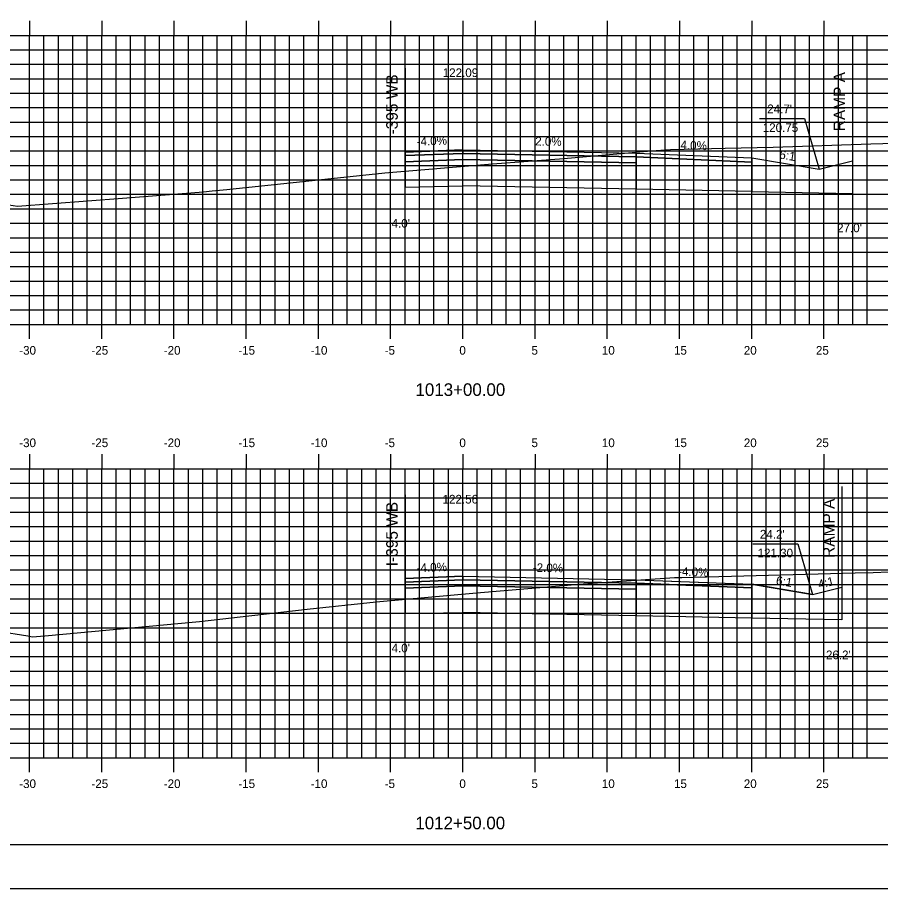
# Model space of a CAD drawing. Extents: x 852625 to 852797, y 365624 to 365734.
# Drawn here: x 852677.7 to 852737.5, y 365624 to 365684.3 of the extents above; entities that cross this region are included whole.
import ezdxf

# ---------------------------------------------------------------- set-up
doc = ezdxf.new("R2010")
doc.units = 0
for name, color, linetype in [('ANNOTATION', 7, 'Continuous'), ('BORDER', 7, 'Continuous'), ('D_Roadway_Centerline', 7, 'Continuous'), ('D_Roadway_Centerline_Text', 7, 'Continuous'), ('D_Roadway_Edge_Shoulder', 7, 'Continuous'), ('D_Roadway_Edge_TW', 7, 'Continuous'), ('D_Roadway_FinishedGrade', 7, 'Continuous'), ('D_Roadway_Pavement', 7, 'Continuous'), ('D_Roadway_SubGrade', 7, 'Continuous'), ('D_Text_Standard', 7, 'Continuous'), ('Default', 7, 'Continuous'), ('H_V ANNOTATION', 7, 'Continuous'), ('MAJOR', 7, 'Continuous'), ('MINOR', 7, 'Continuous'), ('PLOT BOUNDARY', 7, 'Continuous'), ('S_Roadway_Centerline', 7, 'Continuous')]:
    doc.layers.add(name, color=color, linetype=linetype)

msp = doc.modelspace()

# ---------------------------------------------------------------- linework, layer by layer
at = {"layer": 'ANNOTATION'}
for points in [[(852729.095, 365677.281), (852732.205, 365677.281), (852733.216, 365673.776)], [(852728.635, 365647.834), (852731.744, 365647.834), (852732.755, 365644.329)]]:
    msp.add_lwpolyline(points, dxfattribs=at)
at = {"layer": 'BORDER'}
msp.add_lwpolyline([(852633.549, 365627.027), (852793.549, 365627.027), (852793.549, 365732.027), (852633.549, 365732.027)], close=True, dxfattribs=at)
at = {"layer": 'D_Roadway_Centerline'}
for p, q in [((852728.548, 365674.554), (852733.216, 365673.776)), ((852728.548, 365672.214), (852735.524, 365672.088))]:
    msp.add_line(p, q, dxfattribs=at)
for points in [[(852704.548, 365674.954), (852708.548, 365675.114), (852708.55, 365675.114), (852720.549, 365674.874), (852728.548, 365674.554)], [(852733.216, 365673.776), (852735.525, 365674.353)], [(852704.548, 365645.43), (852704.548, 365645.43), (852708.547, 365645.59), (852708.549, 365645.59), (852720.544, 365645.35), (852720.549, 365645.35), (852728.544, 365645.03), (852732.755, 365644.329), (852728.548, 365645.03)], [(852732.755, 365644.329), (852734.789, 365644.837)], [(852734.789, 365642.572), (852728.548, 365642.69)]]:
    msp.add_lwpolyline(points, dxfattribs=at)
at = {"layer": 'D_Roadway_Edge_Shoulder'}
for points in [[(852708.548, 365675.114), (852704.548, 365674.954), (852704.548, 365674.704), (852708.548, 365674.864)], [(852720.548, 365674.874), (852728.548, 365674.554), (852728.548, 365674.26), (852720.549, 365674.624)], [(852708.549, 365645.59), (852704.548, 365645.43), (852704.548, 365645.18), (852708.549, 365645.34)], [(852720.549, 365645.35), (852728.548, 365645.03), (852728.548, 365644.78), (852720.549, 365645.1)]]:
    msp.add_lwpolyline(points, close=True, dxfattribs=at)
at = {"layer": 'D_Roadway_Edge_TW'}
for points in [[(852708.548, 365675.114), (852720.548, 365674.874), (852720.549, 365674.624), (852708.548, 365674.864)], [(852708.549, 365645.59), (852720.549, 365645.35), (852720.549, 365645.1), (852708.549, 365645.34)]]:
    msp.add_lwpolyline(points, close=True, dxfattribs=at)
for points in [[(852720.548, 365674.874), (852720.548, 365674.707)], [(852720.549, 365645.35), (852720.549, 365645.183)]]:
    msp.add_lwpolyline(points, dxfattribs=at)
at = {"layer": 'D_Roadway_FinishedGrade'}
for p, q in [((852708.548, 365675.114), (852708.548, 365674.864)), ((852704.548, 365674.954), (852704.548, 365674.704)), ((852720.549, 365674.874), (852720.549, 365674.624)), ((852728.548, 365674.554), (852728.548, 365674.304)), ((852708.549, 365645.59), (852708.549, 365645.34)), ((852704.548, 365645.43), (852704.548, 365645.18)), ((852720.549, 365645.35), (852720.549, 365645.1)), ((852728.548, 365645.03), (852728.548, 365644.78))]:
    msp.add_line(p, q, dxfattribs=at)
at = {"layer": 'D_Roadway_Pavement'}
for points in [[(852708.548, 365674.864), (852704.548, 365674.704), (852704.548, 365674.287), (852708.548, 365674.447)], [(852708.548, 365674.864), (852720.549, 365674.624), (852720.548, 365674.207), (852708.548, 365674.447)], [(852708.549, 365645.34), (852704.548, 365645.18), (852704.548, 365644.763), (852708.549, 365644.923)], [(852708.549, 365645.34), (852720.549, 365645.1), (852720.549, 365644.683), (852708.549, 365644.923)]]:
    msp.add_lwpolyline(points, close=True, dxfattribs=at)
for points in [[(852720.548, 365674.707), (852720.548, 365674.207)], [(852720.548, 365674.707), (852720.548, 365674.207)], [(852720.549, 365645.183), (852720.549, 365644.683)], [(852720.549, 365645.183), (852720.549, 365644.683)]]:
    msp.add_lwpolyline(points, dxfattribs=at)
at = {"layer": 'D_Roadway_SubGrade'}
for p, q in [((852735.525, 365681.328), (852735.525, 365672.088)), ((852704.548, 365680.765), (852704.548, 365672.534)), ((852734.789, 365651.802), (852734.789, 365642.572)), ((852704.548, 365651.225), (852704.548, 365643.01))]:
    msp.add_line(p, q, dxfattribs=at)
for points in [[(852708.548, 365674.447), (852704.548, 365674.287), (852704.548, 365674.787), (852704.548, 365674.954), (852704.548, 365672.534), (852708.548, 365672.614)], [(852708.548, 365674.447), (852720.548, 365674.207), (852720.548, 365672.374), (852708.548, 365672.614)], [(852720.548, 365674.207), (852720.549, 365674.624), (852728.548, 365674.26), (852728.548, 365674.554), (852728.548, 365672.214), (852720.548, 365672.374)], [(852708.549, 365644.923), (852704.548, 365644.763), (852704.548, 365645.263), (852704.548, 365645.43), (852704.548, 365643.01), (852708.549, 365643.09)], [(852708.549, 365644.923), (852720.549, 365644.683), (852720.549, 365642.85), (852708.549, 365643.09)], [(852720.549, 365644.683), (852720.549, 365645.1), (852728.548, 365644.78), (852728.548, 365645.03), (852728.548, 365642.69), (852720.549, 365642.85)]]:
    msp.add_lwpolyline(points, close=True, dxfattribs=at)
for points in [[(852720.548, 365674.207), (852720.548, 365672.374)], [(852720.549, 365644.683), (852720.549, 365642.85)]]:
    msp.add_lwpolyline(points, dxfattribs=at)
at = {"layer": 'Default'}
for p, q in [((852728.548, 365674.554), (852733.216, 365673.776)), ((852728.548, 365645.03), (852732.755, 365644.329))]:
    msp.add_line(p, q, dxfattribs=at)
at = {"layer": 'MAJOR'}
for p, q in [((852678.548, 365684.029), (852678.548, 365683.027)), ((852683.548, 365684.029), (852683.548, 365683.027)), ((852688.548, 365684.029), (852688.548, 365683.027)), ((852693.548, 365684.029), (852693.548, 365683.027)), ((852698.548, 365684.029), (852698.548, 365683.027)), ((852703.548, 365684.029), (852703.548, 365683.027)), ((852708.548, 365684.029), (852708.548, 365683.027)), ((852713.548, 365684.029), (852713.548, 365683.027)), ((852718.548, 365684.029), (852718.548, 365683.027)), ((852723.548, 365684.029), (852723.548, 365683.027)), ((852728.548, 365684.029), (852728.548, 365683.027)), ((852733.548, 365684.029), (852733.548, 365683.027)), ((852638.548, 365683.027), (852778.548, 365683.027)), ((852638.548, 365683.027), (852778.548, 365683.027)), ((852678.548, 365663.027), (852678.548, 365683.027)), ((852683.548, 365663.027), (852683.548, 365683.027)), ((852688.548, 365663.027), (852688.548, 365683.027)), ((852693.548, 365663.027), (852693.548, 365683.027)), ((852698.548, 365663.027), (852698.548, 365683.027)), ((852703.548, 365663.027), (852703.548, 365683.027)), ((852708.548, 365663.027), (852708.548, 365683.027)), ((852713.548, 365663.027), (852713.548, 365683.027)), ((852718.548, 365663.027), (852718.548, 365683.027)), ((852723.548, 365663.027), (852723.548, 365683.027)), ((852728.548, 365663.027), (852728.548, 365683.027)), ((852733.548, 365663.027), (852733.548, 365683.027)), ((852638.548, 365678.027), (852778.548, 365678.027)), ((852638.548, 365673.027), (852778.548, 365673.027)), ((852638.548, 365668.027), (852778.548, 365668.027)), ((852638.548, 365663.027), (852778.548, 365663.027)), ((852638.548, 365663.027), (852778.548, 365663.027)), ((852678.548, 365662.025), (852678.548, 365663.027)), ((852683.548, 365662.025), (852683.548, 365663.027)), ((852688.548, 365662.025), (852688.548, 365663.027)), ((852693.548, 365662.025), (852693.548, 365663.027)), ((852698.548, 365662.025), (852698.548, 365663.027)), ((852703.548, 365662.025), (852703.548, 365663.027)), ((852708.548, 365662.025), (852708.548, 365663.027)), ((852713.548, 365662.025), (852713.548, 365663.027)), ((852718.548, 365662.025), (852718.548, 365663.027)), ((852723.548, 365662.025), (852723.548, 365663.027)), ((852728.548, 365662.025), (852728.548, 365663.027)), ((852733.548, 365662.025), (852733.548, 365663.027)), ((852678.548, 365654.029), (852678.548, 365653.027)), ((852683.548, 365654.029), (852683.548, 365653.027)), ((852688.548, 365654.029), (852688.548, 365653.027)), ((852693.548, 365654.029), (852693.548, 365653.027)), ((852698.548, 365654.029), (852698.548, 365653.027)), ((852703.548, 365654.029), (852703.548, 365653.027)), ((852708.548, 365654.029), (852708.548, 365653.027)), ((852713.548, 365654.029), (852713.548, 365653.027)), ((852718.548, 365654.029), (852718.548, 365653.027)), ((852723.548, 365654.029), (852723.548, 365653.027)), ((852728.548, 365654.029), (852728.548, 365653.027)), ((852733.548, 365654.029), (852733.548, 365653.027)), ((852638.548, 365653.027), (852778.548, 365653.027)), ((852638.548, 365653.027), (852778.548, 365653.027)), ((852678.548, 365633.027), (852678.548, 365653.027)), ((852683.548, 365633.027), (852683.548, 365653.027)), ((852688.548, 365633.027), (852688.548, 365653.027)), ((852693.548, 365633.027), (852693.548, 365653.027)), ((852698.548, 365633.027), (852698.548, 365653.027)), ((852703.548, 365633.027), (852703.548, 365653.027)), ((852708.548, 365633.027), (852708.548, 365653.027)), ((852713.548, 365633.027), (852713.548, 365653.027)), ((852718.548, 365633.027), (852718.548, 365653.027)), ((852723.548, 365633.027), (852723.548, 365653.027)), ((852728.548, 365633.027), (852728.548, 365653.027)), ((852733.548, 365633.027), (852733.548, 365653.027)), ((852638.548, 365648.027), (852778.548, 365648.027)), ((852638.548, 365643.027), (852778.548, 365643.027)), ((852638.548, 365638.027), (852778.548, 365638.027)), ((852638.548, 365633.027), (852778.548, 365633.027)), ((852638.548, 365633.027), (852778.548, 365633.027)), ((852678.548, 365632.025), (852678.548, 365633.027)), ((852683.548, 365632.025), (852683.548, 365633.027)), ((852688.548, 365632.025), (852688.548, 365633.027)), ((852693.548, 365632.025), (852693.548, 365633.027)), ((852698.548, 365632.025), (852698.548, 365633.027)), ((852703.548, 365632.025), (852703.548, 365633.027)), ((852708.548, 365632.025), (852708.548, 365633.027)), ((852713.548, 365632.025), (852713.548, 365633.027)), ((852718.548, 365632.025), (852718.548, 365633.027)), ((852723.548, 365632.025), (852723.548, 365633.027)), ((852728.548, 365632.025), (852728.548, 365633.027)), ((852733.548, 365632.025), (852733.548, 365633.027))]:
    msp.add_line(p, q, dxfattribs=at)
at = {"layer": 'MINOR'}
for p, q in [((852679.548, 365663.027), (852679.548, 365683.027)), ((852680.548, 365663.027), (852680.548, 365683.027)), ((852681.548, 365663.027), (852681.548, 365683.027)), ((852682.548, 365663.027), (852682.548, 365683.027)), ((852684.548, 365663.027), (852684.548, 365683.027)), ((852685.548, 365663.027), (852685.548, 365683.027)), ((852686.548, 365663.027), (852686.548, 365683.027)), ((852687.548, 365663.027), (852687.548, 365683.027)), ((852689.548, 365663.027), (852689.548, 365683.027)), ((852690.548, 365663.027), (852690.548, 365683.027)), ((852691.548, 365663.027), (852691.548, 365683.027)), ((852692.548, 365663.027), (852692.548, 365683.027)), ((852694.548, 365663.027), (852694.548, 365683.027)), ((852695.548, 365663.027), (852695.548, 365683.027)), ((852696.548, 365663.027), (852696.548, 365683.027)), ((852697.548, 365663.027), (852697.548, 365683.027)), ((852699.548, 365663.027), (852699.548, 365683.027)), ((852700.548, 365663.027), (852700.548, 365683.027)), ((852701.548, 365663.027), (852701.548, 365683.027)), ((852702.548, 365663.027), (852702.548, 365683.027)), ((852704.548, 365663.027), (852704.548, 365683.027)), ((852705.548, 365663.027), (852705.548, 365683.027)), ((852706.548, 365663.027), (852706.548, 365683.027)), ((852707.548, 365663.027), (852707.548, 365683.027)), ((852709.548, 365663.027), (852709.548, 365683.027)), ((852710.548, 365663.027), (852710.548, 365683.027)), ((852711.548, 365663.027), (852711.548, 365683.027)), ((852712.548, 365663.027), (852712.548, 365683.027)), ((852714.548, 365663.027), (852714.548, 365683.027)), ((852715.548, 365663.027), (852715.548, 365683.027)), ((852716.548, 365663.027), (852716.548, 365683.027)), ((852717.548, 365663.027), (852717.548, 365683.027)), ((852719.548, 365663.027), (852719.548, 365683.027)), ((852720.548, 365663.027), (852720.548, 365683.027)), ((852721.548, 365663.027), (852721.548, 365683.027)), ((852722.548, 365663.027), (852722.548, 365683.027)), ((852724.548, 365663.027), (852724.548, 365683.027)), ((852725.548, 365663.027), (852725.548, 365683.027)), ((852726.548, 365663.027), (852726.548, 365683.027)), ((852727.548, 365663.027), (852727.548, 365683.027)), ((852729.548, 365663.027), (852729.548, 365683.027)), ((852730.548, 365663.027), (852730.548, 365683.027)), ((852731.548, 365663.027), (852731.548, 365683.027)), ((852732.548, 365663.027), (852732.548, 365683.027)), ((852734.548, 365663.027), (852734.548, 365683.027)), ((852735.548, 365663.027), (852735.548, 365683.027)), ((852736.548, 365663.027), (852736.548, 365683.027)), ((852638.548, 365682.027), (852778.548, 365682.027)), ((852638.548, 365681.027), (852778.548, 365681.027)), ((852638.548, 365680.027), (852778.548, 365680.027)), ((852638.548, 365679.027), (852778.548, 365679.027)), ((852638.548, 365677.027), (852778.548, 365677.027)), ((852638.548, 365676.027), (852778.548, 365676.027)), ((852638.548, 365675.027), (852778.548, 365675.027)), ((852638.548, 365674.027), (852778.548, 365674.027)), ((852638.548, 365672.027), (852778.548, 365672.027)), ((852638.548, 365671.027), (852778.548, 365671.027)), ((852638.548, 365670.027), (852778.548, 365670.027)), ((852638.548, 365669.027), (852778.548, 365669.027)), ((852638.548, 365667.027), (852778.548, 365667.027)), ((852638.548, 365666.027), (852778.548, 365666.027)), ((852638.548, 365665.027), (852778.548, 365665.027)), ((852638.548, 365664.027), (852778.548, 365664.027)), ((852679.548, 365633.027), (852679.548, 365653.027)), ((852680.548, 365633.027), (852680.548, 365653.027)), ((852681.548, 365633.027), (852681.548, 365653.027)), ((852682.548, 365633.027), (852682.548, 365653.027)), ((852684.548, 365633.027), (852684.548, 365653.027)), ((852685.548, 365633.027), (852685.548, 365653.027)), ((852686.548, 365633.027), (852686.548, 365653.027)), ((852687.548, 365633.027), (852687.548, 365653.027)), ((852689.548, 365633.027), (852689.548, 365653.027)), ((852690.548, 365633.027), (852690.548, 365653.027)), ((852691.548, 365633.027), (852691.548, 365653.027)), ((852692.548, 365633.027), (852692.548, 365653.027)), ((852694.548, 365633.027), (852694.548, 365653.027)), ((852695.548, 365633.027), (852695.548, 365653.027)), ((852696.548, 365633.027), (852696.548, 365653.027)), ((852697.548, 365633.027), (852697.548, 365653.027)), ((852699.548, 365633.027), (852699.548, 365653.027)), ((852700.548, 365633.027), (852700.548, 365653.027)), ((852701.548, 365633.027), (852701.548, 365653.027)), ((852702.548, 365633.027), (852702.548, 365653.027)), ((852704.548, 365633.027), (852704.548, 365653.027)), ((852705.548, 365633.027), (852705.548, 365653.027)), ((852706.548, 365633.027), (852706.548, 365653.027)), ((852707.548, 365633.027), (852707.548, 365653.027)), ((852709.548, 365633.027), (852709.548, 365653.027)), ((852710.548, 365633.027), (852710.548, 365653.027)), ((852711.548, 365633.027), (852711.548, 365653.027)), ((852712.548, 365633.027), (852712.548, 365653.027)), ((852714.548, 365633.027), (852714.548, 365653.027)), ((852715.548, 365633.027), (852715.548, 365653.027)), ((852716.548, 365633.027), (852716.548, 365653.027)), ((852717.548, 365633.027), (852717.548, 365653.027)), ((852719.548, 365633.027), (852719.548, 365653.027)), ((852720.548, 365633.027), (852720.548, 365653.027)), ((852721.548, 365633.027), (852721.548, 365653.027)), ((852722.548, 365633.027), (852722.548, 365653.027)), ((852724.548, 365633.027), (852724.548, 365653.027)), ((852725.548, 365633.027), (852725.548, 365653.027)), ((852726.548, 365633.027), (852726.548, 365653.027)), ((852727.548, 365633.027), (852727.548, 365653.027)), ((852729.548, 365633.027), (852729.548, 365653.027)), ((852730.548, 365633.027), (852730.548, 365653.027)), ((852731.548, 365633.027), (852731.548, 365653.027)), ((852732.548, 365633.027), (852732.548, 365653.027)), ((852734.548, 365633.027), (852734.548, 365653.027)), ((852735.548, 365633.027), (852735.548, 365653.027)), ((852736.548, 365633.027), (852736.548, 365653.027)), ((852638.548, 365652.027), (852778.548, 365652.027)), ((852638.548, 365651.027), (852778.548, 365651.027)), ((852638.548, 365650.027), (852778.548, 365650.027)), ((852638.548, 365649.027), (852778.548, 365649.027)), ((852638.548, 365647.027), (852778.548, 365647.027)), ((852638.548, 365646.027), (852778.548, 365646.027)), ((852638.548, 365645.027), (852778.548, 365645.027)), ((852638.548, 365644.027), (852778.548, 365644.027)), ((852638.548, 365642.027), (852778.548, 365642.027)), ((852638.548, 365641.027), (852778.548, 365641.027)), ((852638.548, 365640.027), (852778.548, 365640.027)), ((852638.548, 365639.027), (852778.548, 365639.027)), ((852638.548, 365637.027), (852778.548, 365637.027)), ((852638.548, 365636.027), (852778.548, 365636.027)), ((852638.548, 365635.027), (852778.548, 365635.027)), ((852638.548, 365634.027), (852778.548, 365634.027))]:
    msp.add_line(p, q, dxfattribs=at)
at = {"layer": 'PLOT BOUNDARY'}
msp.add_lwpolyline([(852625.455, 365623.968), (852795.455, 365623.968), (852795.455, 365733.968), (852625.455, 365733.968)], close=True, dxfattribs=at)
at = {"layer": 'S_Roadway_Centerline'}
for points in [[(852677.118, 365671.306), (852677.72, 365671.197), (852677.724, 365671.197), (852684.993, 365671.772), (852690.593, 365672.202), (852691.185, 365672.264), (852692.207, 365672.371), (852703.137, 365673.518), (852710.604, 365674.128), (852715.547, 365674.501), (852721.597, 365675.028), (852722.93, 365675.127), (852726.7, 365675.222), (852730.043, 365675.301), (852736.804, 365675.513), (852740.95, 365675.63)], [(852638.548, 365645.945), (852641.957, 365645.864), (852643.44, 365645.839), (852651.782, 365645.603), (852653.37, 365645.534), (852654.991, 365645.292), (852659.589, 365644.622), (852668.457, 365643.183), (852676.348, 365641.785), (852678.438, 365641.461), (852678.739, 365641.385), (852679.613, 365641.469), (852690.325, 365642.455), (852697.76, 365643.309), (852702.54, 365643.826), (852709.501, 365644.441), (852716.869, 365645.066), (852723.198, 365645.509), (852723.701, 365645.501), (852735.72, 365645.824), (852736.967, 365645.857), (852738.031, 365645.888)]]:
    msp.add_lwpolyline(points, dxfattribs=at)

# ---------------------------------------------------------------- texts
at = {"layer": 'ANNOTATION'}
for s, height, rotation, p in [('RAMP A', 0.8, 90, (852735.018, 365676.393)), ('I-395 WB', 0.8, 90, (852704.041, 365675.874)), ("24.7' ", 0.6, 360, (852729.624, 365677.644)), ('120.75', 0.6, 360, (852729.313, 365676.344)), ('-4.0%', 0.6, 2.29041, (852705.365, 365675.387)), ('2.0%', 0.6, 358.85423, (852713.553, 365675.414)), ('4.0%', 0.6, 357.70931, (852723.605, 365675.152)), ('6:1', 0.6, 350.53768, (852730.428, 365674.511)), ('RAMP A', 0.8, 90, (852734.283, 365646.86)), ('I-395 WB', 0.8, 90, (852704.041, 365646.279)), ("24.2' ", 0.6, 360, (852729.115, 365648.197)), ('121.30', 0.6, 360, (852728.957, 365646.897)), ('-4.0%', 0.6, 2.29049, (852705.364, 365645.863)), ('-2.0%', 0.6, 358.85425, (852713.389, 365645.893)), ('-4.0%', 0.6, 357.70935, (852723.442, 365645.635)), ('6:1', 0.6, 350.53754, (852730.198, 365645.025)), ('4:1', 0.6, 14.03407, (852733.218, 365644.719))]:
    msp.add_text(s, height=height, rotation=rotation, dxfattribs=at).set_placement(p)
at = {"layer": 'D_Roadway_Centerline'}
for s, p in [('C', (852708.543, 365675.114)), ('L', (852708.548, 365675.106)), ('C', (852708.543, 365645.59)), ('L', (852708.549, 365645.583))]:
    msp.add_text(s, height=0.0146, dxfattribs=at).set_placement(p)
at = {"layer": 'D_Roadway_Centerline_Text'}
for s, p in [('122.09', (852707.157, 365680.146)), ('122.56', (852707.146, 365650.622))]:
    msp.add_text(s, height=0.6, dxfattribs=at).set_placement(p)
at = {"layer": 'D_Text_Standard'}
for s, p in [("4.0'", (852703.615, 365669.719)), ("27.0'", (852734.463, 365669.404)), ("4.0'", (852703.615, 365640.318)), ("26.2'", (852733.69, 365639.845))]:
    msp.add_text(s, height=0.6, dxfattribs=at).set_placement(p)
at = {"layer": 'H_V ANNOTATION'}
for s, height, p in [('-30', 0.6, (852677.837, 365660.927)), ('-25', 0.6, (852682.834, 365660.927)), ('-20', 0.6, (852687.842, 365660.927)), ('-15', 0.6, (852693.005, 365660.927)), ('-10', 0.6, (852698.013, 365660.927)), ('-5', 0.6, (852703.139, 365660.927)), ('0', 0.6, (852708.307, 365660.927)), ('5', 0.6, (852713.299, 365660.927)), ('10', 0.6, (852718.174, 365660.927)), ('15', 0.6, (852723.166, 365660.927)), ('20', 0.6, (852728.002, 365660.927)), ('25', 0.6, (852732.994, 365660.927)), ('1013+00.00', 0.875, (852705.271, 365658.07)), ('-30', 0.6, (852677.837, 365654.527)), ('-25', 0.6, (852682.834, 365654.527)), ('-20', 0.6, (852687.842, 365654.527)), ('-15', 0.6, (852693.005, 365654.527)), ('-10', 0.6, (852698.013, 365654.527)), ('-5', 0.6, (852703.139, 365654.527)), ('0', 0.6, (852708.307, 365654.527)), ('5', 0.6, (852713.299, 365654.527)), ('10', 0.6, (852718.174, 365654.527)), ('15', 0.6, (852723.166, 365654.527)), ('20', 0.6, (852728.002, 365654.527)), ('25', 0.6, (852732.994, 365654.527)), ('-30', 0.6, (852677.837, 365630.927)), ('-25', 0.6, (852682.834, 365630.927)), ('-20', 0.6, (852687.842, 365630.927)), ('-15', 0.6, (852693.005, 365630.927)), ('-10', 0.6, (852698.013, 365630.927)), ('-5', 0.6, (852703.139, 365630.927)), ('0', 0.6, (852708.307, 365630.927)), ('5', 0.6, (852713.299, 365630.927)), ('10', 0.6, (852718.174, 365630.927)), ('15', 0.6, (852723.166, 365630.927)), ('20', 0.6, (852728.002, 365630.927)), ('25', 0.6, (852732.994, 365630.927)), ('1012+50.00', 0.875, (852705.263, 365628.07))]:
    msp.add_text(s, height=height, dxfattribs=at).set_placement(p)

doc.saveas('drawing.dxf')
